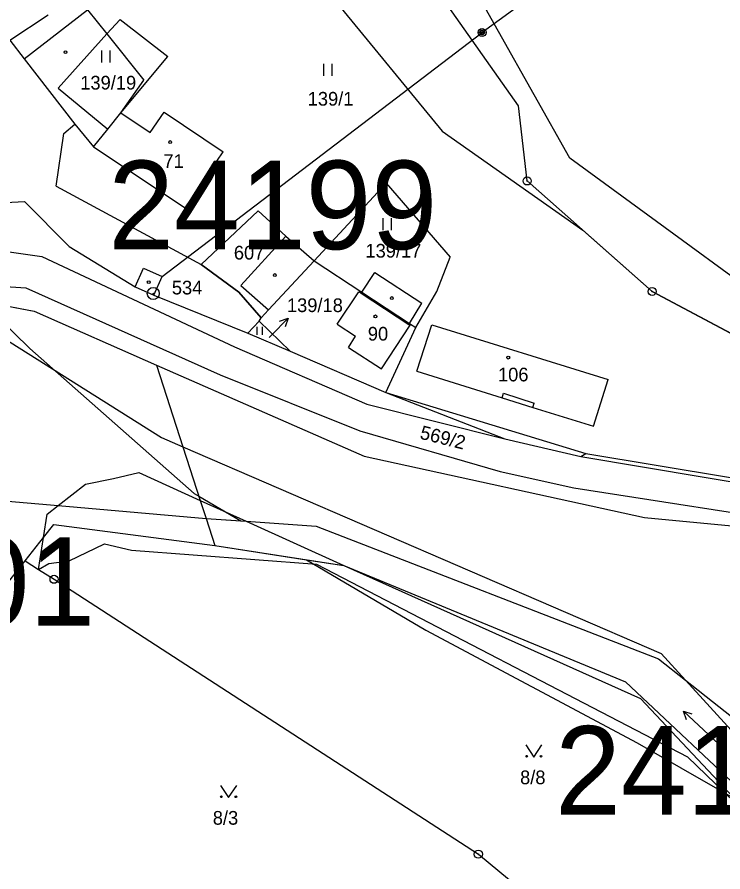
# Model space of a CAD drawing. Extents: x -725765 to -723182, y -1052705 to -1049154.
# Drawn here: x -724674.7 to -724587, y -1050715 to -1050608.8 of the extents above; entities that cross this region are included whole.
import ezdxf

# ---------------------------------------------------------------- set-up
doc = ezdxf.new("R2010")
doc.units = 0
for name, color, linetype in [('Vrstva 1', 7, 'Continuous'), ('Vrstva 12', 7, 'Continuous'), ('Vrstva 16', 7, 'Continuous'), ('Vrstva 17', 7, 'Continuous'), ('Vrstva 18', 7, 'Continuous'), ('Vrstva 19', 7, 'Continuous'), ('Vrstva 25', 7, 'Continuous'), ('Vrstva 4', 7, 'Continuous'), ('Vrstva 52', 7, 'Continuous'), ('Vrstva 53', 7, 'Continuous')]:
    doc.layers.add(name, color=color, linetype=linetype)

msp = doc.modelspace()

# ---------------------------------------------------------------- linework, layer by layer
at = {"layer": 'Vrstva 1'}
for points in [[(-724605.98, -1050626.34), (-724619.3, -1050602.68)], [(-724612.36, -1050619.85), (-724622.11, -1050606.03)], [(-724675.63, -1050611.7), (-724670.87, -1050608.53)], [(-724663.55, -1050610.92), (-724661.92, -1050609.11)], [(-724661.92, -1050609.11), (-724656, -1050613.72)], [(-724669.62, -1050617.66), (-724663.55, -1050610.92)], [(-724661.84, -1050620.71), (-724656, -1050613.72)], [(-724669.62, -1050617.66), (-724663.46, -1050622.74)], [(-724611.3, -1050629.18), (-724612.36, -1050619.85)], [(-724663.46, -1050622.74), (-724661.84, -1050620.71)], [(-724661.84, -1050620.71), (-724658.17, -1050623.17)], [(-724658.17, -1050623.17), (-724656.44, -1050620.63)], [(-724656.44, -1050620.63), (-724649.08, -1050625.54)], [(-724665.22, -1050624.94), (-724663.46, -1050622.74)], [(-724665.22, -1050624.94), (-724653.83, -1050632.52)], [(-724653.83, -1050632.52), (-724649.08, -1050625.54)], [(-724571.98, -1050651.19), (-724605.98, -1050626.34)], [(-724637.8, -1050639.1), (-724628.82, -1050629.45)], [(-724628.82, -1050629.45), (-724620.88, -1050638.63)], [(-724595.76, -1050642.91), (-724611.3, -1050629.18)], [(-724676.18, -1050631.86), (-724673.79, -1050631.74)], [(-724673.79, -1050631.74), (-724668.24, -1050637.31)], [(-724651.84, -1050639.57), (-724644.75, -1050632.89)], [(-724644.75, -1050632.89), (-724641.29, -1050636.04)], [(-724641.29, -1050636.04), (-724637.8, -1050639.1)], [(-724668.24, -1050637.31), (-724660.03, -1050642.33)], [(-724643.47, -1050645.2), (-724637.8, -1050639.1)], [(-724637.8, -1050639.1), (-724631.86, -1050643)], [(-724622.52, -1050642.91), (-724620.88, -1050638.63)], [(-724651.84, -1050639.57), (-724647.16, -1050643)], [(-724660.03, -1050642.33), (-724657.72, -1050643.37)], [(-724684.55, -1050643.07), (-724672.59, -1050645.36)], [(-724657.72, -1050643.37), (-724646.03, -1050648.07)], [(-724647.16, -1050643), (-724644.36, -1050646.2)], [(-724631.86, -1050643), (-724625.94, -1050646.88)], [(-724625.16, -1050647.39), (-724622.52, -1050642.91)], [(-724565.49, -1050658.98), (-724595.76, -1050642.91)], [(-724672.59, -1050645.36), (-724657.37, -1050652.05)], [(-724644.36, -1050646.2), (-724643.47, -1050645.2)], [(-724646.03, -1050648.07), (-724644.62, -1050646.61)], [(-724644.62, -1050646.61), (-724644.36, -1050646.2)], [(-724644.62, -1050646.61), (-724640.75, -1050650.32)], [(-724628.88, -1050655.45), (-724625.16, -1050647.39)], [(-724625.94, -1050646.88), (-724625.16, -1050647.39)], [(-724625.03, -1050652.82), (-724623.17, -1050647.05)], [(-724623.17, -1050647.05), (-724601.24, -1050653.83)], [(-724646.03, -1050648.07), (-724640.75, -1050650.32)], [(-724640.75, -1050650.32), (-724628.88, -1050655.45)], [(-724657.37, -1050652.05), (-724654.1, -1050662.2)], [(-724657.37, -1050652.05), (-724631.58, -1050663.38)], [(-724625.03, -1050652.82), (-724614.41, -1050656.12)], [(-724603.04, -1050659.66), (-724601.24, -1050653.83)], [(-724628.88, -1050655.45), (-724603.99, -1050663.05)], [(-724614.41, -1050656.12), (-724610.59, -1050657.31)], [(-724610.59, -1050657.31), (-724603.04, -1050659.66)], [(-724654.1, -1050662.2), (-724651.95, -1050668.87)], [(-724631.58, -1050663.38), (-724596.72, -1050670.98)], [(-724603.99, -1050663.05), (-724559.78, -1050670.37)], [(-724683.61, -1050668.28), (-724669.61, -1050669.51)], [(-724651.95, -1050668.87), (-724651.23, -1050671.11)], [(-724669.61, -1050669.51), (-724651.23, -1050671.11)], [(-724651.23, -1050671.11), (-724646.24, -1050671.46)], [(-724651.23, -1050671.11), (-724650.15, -1050674.46)], [(-724596.72, -1050670.98), (-724584.97, -1050672.11)], [(-724671.44, -1050673.47), (-724670.16, -1050671.86)], [(-724670.16, -1050671.86), (-724650.15, -1050674.46)], [(-724646.24, -1050671.46), (-724637.53, -1050672.06)], [(-724637.53, -1050672.06), (-724594.97, -1050688.56)], [(-724673.73, -1050676.36), (-724671.44, -1050673.47)], [(-724650.15, -1050674.46), (-724634.1, -1050676.96)], [(-724699.64, -1050709.04), (-724673.73, -1050676.36)], [(-724673.73, -1050676.36), (-724672.06, -1050677.44)], [(-724672.06, -1050677.44), (-724670.13, -1050678.67)], [(-724634.1, -1050676.96), (-724599.06, -1050691.42)], [(-724670.13, -1050678.67), (-724617.37, -1050712.82)], [(-724594.97, -1050688.56), (-724591.6, -1050691.22)], [(-724591.6, -1050691.22), (-724577.38, -1050702.42)], [(-724599.06, -1050691.42), (-724583.1, -1050706.42)], [(-724617.37, -1050712.82), (-724606.3, -1050721.96)]]:
    msp.add_lwpolyline(points, dxfattribs=at)
at = {"layer": 'Vrstva 12'}
for points in [[(-724571.02, -1050577.44), (-724616.91, -1050610.74)], [(-724656.69, -1050641.03), (-724616.91, -1050610.74)]]:
    msp.add_lwpolyline(points, dxfattribs=at)
at = {"layer": 'Vrstva 16'}
msp.add_lwpolyline([(-724643.39, -1050648.61), (-724643.14, -1050648.36)], dxfattribs=at)
at = {"layer": 'Vrstva 25'}
for points in [[(-724664.18, -1050614.48), (-724664.18, -1050612.98)], [(-724663.14, -1050614.48), (-724663.14, -1050612.98)], [(-724636.59, -1050616.12), (-724636.59, -1050614.62)], [(-724635.55, -1050616.12), (-724635.55, -1050614.62)], [(-724629.22, -1050635.29), (-724629.22, -1050633.79)], [(-724628.18, -1050635.29), (-724628.18, -1050633.79)], [(-724643.14, -1050648.36), (-724641.03, -1050646.23)], [(-724642.09, -1050646.59), (-724641.03, -1050646.23), (-724641.38, -1050647.29)], [(-724644.89, -1050648.31), (-724644.89, -1050647.31)], [(-724644.19, -1050648.31), (-724644.19, -1050647.31)], [(-724591.49, -1050696.12), (-724591.88, -1050695.07), (-724590.81, -1050695.39)], [(-724587.48, -1050699.15), (-724591.88, -1050695.07)], [(-724611.47, -1050699.25), (-724610.47, -1050700.75), (-724609.47, -1050699.25)], [(-724649.42, -1050704.29), (-724648.42, -1050705.79), (-724647.42, -1050704.29)]]:
    msp.add_lwpolyline(points, dxfattribs=at)
for centre, radius in [((-724616.91, -1050610.74), 0.5), ((-724616.91, -1050610.74), 0.3), ((-724616.91, -1050610.74), 0.15), ((-724668.7, -1050613.17), 0.175), ((-724655.69, -1050624.34), 0.175), ((-724611.3, -1050629.18), 0.5), ((-724611.3, -1050629.18), 0.032), ((-724642.67, -1050640.87), 0.175), ((-724658.36, -1050641.75), 0.175), ((-724657.79, -1050643.16), 0.75), ((-724595.76, -1050642.91), 0.5), ((-724657.79, -1050643.16), 0.032), ((-724628.12, -1050643.73), 0.175), ((-724595.76, -1050642.91), 0.032), ((-724630.17, -1050646), 0.175), ((-724613.65, -1050651.13), 0.175), ((-724670.13, -1050678.67), 0.5), ((-724670.13, -1050678.67), 0.032), ((-724611.37, -1050700.65), 0.1), ((-724609.57, -1050700.65), 0.1), ((-724649.32, -1050705.69), 0.1), ((-724647.52, -1050705.69), 0.1), ((-724617.37, -1050712.82), 0.5), ((-724617.37, -1050712.82), 0.032)]:
    msp.add_circle(centre, radius, dxfattribs=at)
at = {"layer": 'Vrstva 4'}
for points in [[(-724673.83, -1050614.01), (-724665.98, -1050607.91)], [(-724665.98, -1050607.91), (-724663.55, -1050610.92)], [(-724675.63, -1050611.7), (-724673.83, -1050614.01)], [(-724663.55, -1050610.92), (-724658.95, -1050616.64)], [(-724673.83, -1050614.01), (-724667.56, -1050622.12)], [(-724661.84, -1050620.71), (-724658.95, -1050616.64)], [(-724668.91, -1050623.3), (-724667.56, -1050622.12)], [(-724667.56, -1050622.12), (-724665.22, -1050624.94)], [(-724669.85, -1050629.83), (-724668.91, -1050623.3)], [(-724669.85, -1050629.83), (-724651.84, -1050639.57)], [(-724646.89, -1050642.17), (-724641.29, -1050636.04)], [(-724686.99, -1050636.37), (-724671.63, -1050638.57)], [(-724671.63, -1050638.57), (-724647.7, -1050649.78)], [(-724660.03, -1050642.33), (-724659.01, -1050640.01)], [(-724659.01, -1050640.01), (-724656.69, -1050641.03)], [(-724657.72, -1050643.37), (-724656.69, -1050641.03)], [(-724631.86, -1050643), (-724630.26, -1050640.55)], [(-724630.26, -1050640.55), (-724624.4, -1050644.37)], [(-724686.9, -1050641.59), (-724673.62, -1050642.44)], [(-724673.62, -1050642.44), (-724649.47, -1050653.27)], [(-724646.89, -1050642.17), (-724643.47, -1050645.2)], [(-724634.92, -1050646.99), (-724632.22, -1050642.95)], [(-724632.22, -1050642.95), (-724631.95, -1050643.13)], [(-724631.95, -1050643.13), (-724631.86, -1050643)], [(-724631.95, -1050643.13), (-724626.02, -1050647)], [(-724625.94, -1050646.88), (-724624.4, -1050644.37)], [(-724634.92, -1050646.99), (-724632.63, -1050648.47)], [(-724629.41, -1050652.52), (-724625.85, -1050647.11)], [(-724626.02, -1050647), (-724625.94, -1050646.88)], [(-724626.02, -1050647), (-724625.85, -1050647.11)], [(-724677.53, -1050648.02), (-724656.77, -1050661.05)], [(-724633.53, -1050649.86), (-724632.63, -1050648.47)], [(-724647.7, -1050649.78), (-724631.25, -1050656.91)], [(-724633.53, -1050649.86), (-724629.41, -1050652.52)], [(-724649.47, -1050653.27), (-724632.12, -1050660.23)], [(-724628.88, -1050655.45), (-724614.09, -1050661.2)], [(-724614.41, -1050656.12), (-724614.23, -1050655.55)], [(-724614.23, -1050655.55), (-724610.43, -1050656.79)], [(-724631.25, -1050656.91), (-724614.09, -1050661.2)], [(-724610.59, -1050657.31), (-724610.43, -1050656.79)], [(-724632.12, -1050660.23), (-724614.65, -1050665.28)], [(-724656.77, -1050661.05), (-724654.1, -1050662.2)], [(-724614.09, -1050661.2), (-724604.62, -1050663.41)], [(-724654.1, -1050662.2), (-724594.62, -1050687.91)], [(-724604.62, -1050663.41), (-724603.99, -1050663.05)], [(-724604.62, -1050663.41), (-724574.21, -1050668.52)], [(-724662.74, -1050666.14), (-724659.59, -1050665.41)], [(-724659.59, -1050665.41), (-724651.95, -1050668.87)], [(-724614.65, -1050665.28), (-724605.48, -1050667.3)], [(-724669.61, -1050669.51), (-724666.21, -1050666.86)], [(-724666.21, -1050666.86), (-724662.74, -1050666.14)], [(-724605.48, -1050667.3), (-724575.12, -1050672.03)], [(-724651.95, -1050668.87), (-724646.24, -1050671.46)], [(-724670.99, -1050670.59), (-724669.61, -1050669.51)], [(-724671.44, -1050673.47), (-724670.99, -1050670.59)], [(-724646.24, -1050671.46), (-724634.1, -1050676.96)], [(-724672.06, -1050677.44), (-724671.44, -1050673.47)], [(-724668.26, -1050676.36), (-724663.84, -1050674.28)], [(-724663.84, -1050674.28), (-724660.49, -1050675.07)], [(-724660.49, -1050675.07), (-724637.51, -1050676.79)], [(-724670.79, -1050676.7), (-724668.26, -1050676.36)], [(-724672.06, -1050677.44), (-724670.79, -1050676.7)], [(-724637.51, -1050676.79), (-724591.38, -1050700.73)], [(-724634.1, -1050676.96), (-724597.21, -1050693.47)], [(-724594.62, -1050687.91), (-724591.6, -1050691.22)], [(-724591.6, -1050691.22), (-724558.8, -1050727.1)], [(-724597.21, -1050693.47), (-724564.23, -1050728.57)], [(-724591.38, -1050700.73), (-724583.24, -1050708.55)]]:
    msp.add_lwpolyline(points, dxfattribs=at)
at = {"layer": 'Vrstva 52'}
for points in [[(-724635, -1050607), (-724621.88, -1050623), (-724604.38, -1050635.29), (-724595.76, -1050642.91), (-724580.19, -1050651.18), (-724575.88, -1050654), (-724559.88, -1050664), (-724550.57, -1050672.47)], [(-724690.68, -1050632.92), (-724688.97, -1050632.79), (-724676.18, -1050631.86), (-724673.79, -1050631.74), (-724668.24, -1050637.31), (-724660.03, -1050642.33), (-724657.72, -1050643.37), (-724646.03, -1050648.07), (-724640.75, -1050650.32), (-724628.88, -1050655.45), (-724603.99, -1050663.05), (-724559.78, -1050670.37), (-724550.57, -1050672.47)], [(-724641.29, -1050636.04), (-724637.8, -1050639.1), (-724643.47, -1050645.2), (-724644.36, -1050646.2), (-724647.16, -1050643), (-724651.84, -1050639.57), (-724644.75, -1050632.89), (-724641.29, -1050636.04)], [(-724679.19, -1050644.1), (-724673.13, -1050650), (-724652.69, -1050668), (-724652.12, -1050668.33), (-724646.9, -1050671.41)], [(-724679.19, -1050644.1), (-724672.59, -1050645.36), (-724657.37, -1050652.05), (-724631.58, -1050663.38), (-724596.72, -1050670.98), (-724584.97, -1050672.11), (-724576.17, -1050672.95), (-724537.94, -1050683.93)], [(-724724.39, -1050718.17), (-724717.58, -1050708.46), (-724683.61, -1050668.28), (-724669.61, -1050669.51), (-724651.23, -1050671.11), (-724646.9, -1050671.41)], [(-724733.3, -1050722.26), (-724732.9, -1050722.45), (-724729.65, -1050723.98), (-724725.26, -1050726.05), (-724717.47, -1050725.76), (-724716.99, -1050722.76), (-724701.57, -1050710.63), (-724699.64, -1050709.04), (-724673.73, -1050676.36), (-724671.44, -1050673.47), (-724670.16, -1050671.86), (-724650.15, -1050674.46), (-724638.72, -1050676.24)], [(-724646.9, -1050671.41), (-724646.24, -1050671.46), (-724637.53, -1050672.06), (-724594.97, -1050688.56), (-724591.6, -1050691.22), (-724577.38, -1050702.42), (-724566.08, -1050717.43)], [(-724638.72, -1050676.24), (-724634.1, -1050676.96), (-724599.06, -1050691.42), (-724583.1, -1050706.42), (-724581.64, -1050708.13)], [(-724638.72, -1050676.24), (-724623.88, -1050685), (-724597.63, -1050699), (-724581.64, -1050708.13)]]:
    msp.add_lwpolyline(points, dxfattribs=at)

# ---------------------------------------------------------------- texts
at = {"layer": 'Vrstva 16'}
msp.add_text('139/18', height=1.7, dxfattribs=at).set_placement((-724641.17, -1050645.47))
at = {"layer": 'Vrstva 17'}
msp.add_text('534', height=1.7, dxfattribs=at).set_placement((-724655.48, -1050643.28))
at = {"layer": 'Vrstva 18'}
for s, height, p in [('139/19', 1.7, (-724666.87, -1050617.82)), ('139/1', 1.7, (-724638.59, -1050619.82)), ('139/17', 1.7, (-724631.41, -1050638.7)), ('607', 1.7, (-724647.77, -1050638.94)), ('139/18', 0.1, (-724643.19, -1050648.41)), ('8/8', 1.7, (-724612.18, -1050704.13)), ('8/3', 1.7, (-724650.39, -1050709.16))]:
    msp.add_text(s, height=height, dxfattribs=at).set_placement(p)
msp.add_text('569/2', height=1.7, rotation=345.9028, dxfattribs=at).set_placement((-724624.74, -1050661.18))
at = {"layer": 'Vrstva 19'}
for s, p in [('71', (-724656.53, -1050627.56)), ('90', (-724631.11, -1050649.01)), ('106', (-724614.93, -1050654.08))]:
    msp.add_text(s, height=1.7, dxfattribs=at).set_placement(p)
at = {"layer": 'Vrstva 53'}
for s, p in [('24199', (-724663.39, -1050637.66)), ('27001', (-724705.92, -1050684.44)), ('24199', (-724607.83, -1050707.91))]:
    msp.add_text(s, height=11, dxfattribs=at).set_placement(p)

doc.saveas('drawing.dxf')
